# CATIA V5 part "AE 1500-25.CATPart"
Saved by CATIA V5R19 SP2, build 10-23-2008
Part number: AE 1500-25
Bounding box of the stored display mesh (mm): x -37.351 to 37.351, y -37.351 to 37.351, z 0 to 110
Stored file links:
  C:\Users\Bora\Desktop\3D Katı model\AE serisi\AE 1500\AE 1500-25.CATPart
  C:\Program Files\Dassault Systemes\B19\intel_a\reffiles\standard\MetricThickPitch.txt
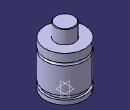
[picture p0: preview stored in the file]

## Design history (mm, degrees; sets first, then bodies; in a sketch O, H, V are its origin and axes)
Body1 (main body)
  Sketch1 on yz-plane, origin (0, 0, 0), H (0, 1, 0), V (0, 0, 1)
    point P1 (37.5, 68.5)
    point P5 (18, 109)
    point P7 (18, 109)
    point P12 (37.5, 63.5)
    point P13 (37.5, 68.5)
    point P14 (37.5, 63.5)
    line L1 (37.5, 68.5) -> (37.5, 84)
    line L2 (37.5, 0) -> (37.5, 8)
    arc A1 centre (17, 109) radius 1 from (18, 109) to (17, 110) ccw
    line L3 (18, 109) -> (18, 84)
    line L4 (33.5, 15) -> (33.5, 8)
    line L5 (37.5, 15) -> (37.5, 63.5)
    arc A2 centre (37.5, 66) radius 2.5 from (37.5, 68.5) to (37.5, 63.5) ccw
    line L6 (17, 110) -> (0, 110)
    point P15 (0, 110)
    line L7 (18, 84) -> (37.5, 84)
    line L8 (0, 0) -> (37.5, 0)
    line L9 (33.5, 15) -> (37.5, 15)
    line L10 (33.5, 8) -> (37.5, 8)
    coincidence: P15 V, P1 P13, P5 P7, P12 P14
    tangency: L6 A1
    horizontal: L7 H, L8 H, L9 H, L10 H
  Shaft1: profile Sketch1, axis Sketch1.V, angle 360
  Sketch2 on face of Shaft1 from Sketch1.L8, origin (0, 0, 0), H (1, 0, 0), V (0, -1, 0)
    point P1 (20, 0)
    distance P1 V = 20
  Hole1: placed by Sketch2, at (20, 0, 0) direction (0, 0, 1), diameter 6.647, depth 13, threaded "M8", thread diameter 8, thread depth 13, pitch 1.25
  CircPattern1: of Hole1, instances 4, angular step 90, axis from xy-plane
